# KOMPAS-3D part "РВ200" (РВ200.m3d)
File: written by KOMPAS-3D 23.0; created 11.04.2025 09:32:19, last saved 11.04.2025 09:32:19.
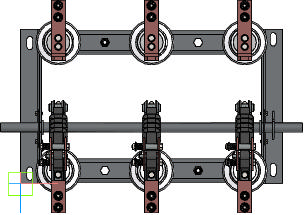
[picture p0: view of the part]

Document properties: Автор: pc; Полное имя файла: C:\Users\pc\Desktop\работа\РВЗ\3D макеты\РВ200.m3d

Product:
- Body: Тело 1
    Масса: 0.01131
- Body: Тело 2
    Масса: 0.01131
- Body: Тело 3
    Масса: 0.01131
- Body: Тело 4
    Масса: 0.011176
- Body: Тело 5
    Масса: 1.60238
- Part/product: РВ200
    Масса: 1.647485

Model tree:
1. Операция без истории:1
2. Операция без истории:2
3. Операция без истории:3
4. Операция без истории:4
5. Операция без истории:5
6. Поверхность без истории:1
7. Поверхность без истории:2
8. Поверхность без истории:3
9. Поверхность без истории:4
10. Поверхность без истории:5
11. Поверхность без истории:6
12. Поверхность без истории:7
13. Поверхность без истории:8
14. Поверхность без истории:9
15. Поверхность без истории:10
16. Поверхность без истории:11
17. Поверхность без истории:12
18. Поверхность без истории:13
19. Поверхность без истории:14
20. Поверхность без истории:15
21. Поверхность без истории:16
22. Поверхность без истории:17
23. Поверхность без истории:18
24. Поверхность без истории:19
25. Поверхность без истории:20
26. Поверхность без истории:21
27. Поверхность без истории:22
28. Поверхность без истории:23
29. Поверхность без истории:24
30. Поверхность без истории:25
31. Поверхность без истории:26
32. Поверхность без истории:27
33. Поверхность без истории:28
34. Поверхность без истории:29
35. Поверхность без истории:30
36. Поверхность без истории:31
37. Поверхность без истории:32
38. Поверхность без истории:33
39. Поверхность без истории:34
40. Поверхность без истории:35
41. Поверхность без истории:36
42. Поверхность без истории:37
43. Поверхность без истории:38
44. Поверхность без истории:39
45. Поверхность без истории:40
46. Поверхность без истории:41
47. Поверхность без истории:42
48. Поверхность без истории:43
49. Поверхность без истории:44
50. Поверхность без истории:45
51. Поверхность без истории:46
52. Поверхность без истории:47
53. Поверхность без истории:48
54. Поверхность без истории:49
55. Поверхность без истории:50
56. Поверхность без истории:51
57. Поверхность без истории:52
58. Поверхность без истории:53
59. Поверхность без истории:54
60. Поверхность без истории:55
61. Поверхность без истории:56
62. Поверхность без истории:57
63. Поверхность без истории:58
64. Поверхность без истории:59
65. Поверхность без истории:60
66. Поверхность без истории:61
67. Поверхность без истории:62
68. Поверхность без истории:63
69. Поверхность без истории:64
70. Поверхность без истории:65
71. Поверхность без истории:66
72. Поверхность без истории:67
73. Поверхность без истории:68
74. Поверхность без истории:69
75. Поверхность без истории:70
76. Поверхность без истории:71
77. Поверхность без истории:72
78. Поверхность без истории:73
79. Поверхность без истории:74
80. Поверхность без истории:75
81. Поверхность без истории:76
82. Поверхность без истории:77
83. Поверхность без истории:78
84. Поверхность без истории:79
85. Поверхность без истории:80
86. Поверхность без истории:81
87. Поверхность без истории:82
88. Поверхность без истории:83
89. Поверхность без истории:84
90. Поверхность без истории:85
91. Поверхность без истории:86
92. Поверхность без истории:87
93. Поверхность без истории:88
94. Поверхность без истории:89
95. Поверхность без истории:90
96. Поверхность без истории:91
97. Поверхность без истории:92
98. Поверхность без истории:93
99. Поверхность без истории:94
100. Поверхность без истории:95
101. Поверхность без истории:96
102. Поверхность без истории:97
103. Поверхность без истории:98
104. Поверхность без истории:99
105. Поверхность без истории:100
106. Поверхность без истории:101
107. Поверхность без истории:102
108. Поверхность без истории:103
109. Поверхность без истории:104
110. Поверхность без истории:105
111. Поверхность без истории:106
112. Поверхность без истории:107
113. Поверхность без истории:108
114. Поверхность без истории:109
115. Поверхность без истории:110
116. Поверхность без истории:111
117. Поверхность без истории:112
118. Поверхность без истории:113
119. Поверхность без истории:114
120. Поверхность без истории:115
121. Поверхность без истории:116
122. Поверхность без истории:117
123. Поверхность без истории:118
124. Поверхность без истории:119
125. Поверхность без истории:120
126. Поверхность без истории:121
127. Поверхность без истории:122
128. Поверхность без истории:123
129. Поверхность без истории:124
130. Поверхность без истории:125
131. Поверхность без истории:126
132. Поверхность без истории:127
133. Поверхность без истории:128
134. Поверхность без истории:129
135. Поверхность без истории:130
136. Поверхность без истории:131
137. Поверхность без истории:132
138. Поверхность без истории:133
139. Поверхность без истории:134
140. Поверхность без истории:135
141. Поверхность без истории:136
142. Поверхность без истории:137
143. Поверхность без истории:138
144. Поверхность без истории:139
145. Поверхность без истории:140
146. Поверхность без истории:141
147. Поверхность без истории:142
148. Поверхность без истории:143
149. Поверхность без истории:144
150. Поверхность без истории:145
151. Поверхность без истории:146
152. Поверхность без истории:147
153. Поверхность без истории:148
154. Поверхность без истории:149
155. Поверхность без истории:150
156. Поверхность без истории:151
157. Поверхность без истории:152
158. Поверхность без истории:153
159. Поверхность без истории:154
160. Поверхность без истории:155
161. Поверхность без истории:156
162. Поверхность без истории:157
163. Поверхность без истории:158
164. Поверхность без истории:159
165. Поверхность без истории:160
166. Поверхность без истории:161
167. Поверхность без истории:162
168. Поверхность без истории:163
169. Поверхность без истории:164
170. Поверхность без истории:165
171. Поверхность без истории:166
172. Поверхность без истории:167
173. Поверхность без истории:168
174. Поверхность без истории:169
175. Поверхность без истории:170
176. Поверхность без истории:171
177. Поверхность без истории:172
178. Поверхность без истории:173
179. Поверхность без истории:174
180. Поверхность без истории:175
181. Поверхность без истории:176
182. Поверхность без истории:177
183. Поверхность без истории:178
184. Поверхность без истории:179
185. Поверхность без истории:180
186. Поверхность без истории:181
187. Поверхность без истории:182
188. Поверхность без истории:183
189. Поверхность без истории:184
190. Поверхность без истории:185
191. Поверхность без истории:186
192. Поверхность без истории:187
193. Поверхность без истории:188
194. Поверхность без истории:189
195. Поверхность без истории:190
196. Поверхность без истории:191
197. Поверхность без истории:192
198. Поверхность без истории:193
199. Поверхность без истории:194
200. Поверхность без истории:195
201. Поверхность без истории:196
202. Поверхность без истории:197
203. Поверхность без истории:198
204. Поверхность без истории:199
205. Поверхность без истории:200
206. Поверхность без истории:201
207. Поверхность без истории:202
208. Поверхность без истории:203
209. Поверхность без истории:204
210. Поверхность без истории:205
211. Поверхность без истории:206
212. Поверхность без истории:207
213. Поверхность без истории:208
214. Поверхность без истории:209
215. Поверхность без истории:210
216. Поверхность без истории:211
217. Поверхность без истории:212
218. Поверхность без истории:213
219. Поверхность без истории:214
220. Поверхность без истории:215
221. Поверхность без истории:216
222. Поверхность без истории:217
223. Поверхность без истории:218
224. Поверхность без истории:219
225. Поверхность без истории:220
226. Поверхность без истории:221
227. Поверхность без истории:222
228. Поверхность без истории:223
229. Поверхность без истории:224
230. Поверхность без истории:225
